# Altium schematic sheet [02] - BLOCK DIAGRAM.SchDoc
size A3; DocumentNumber: 2; SheetNumber: 2; SheetTotal: 4
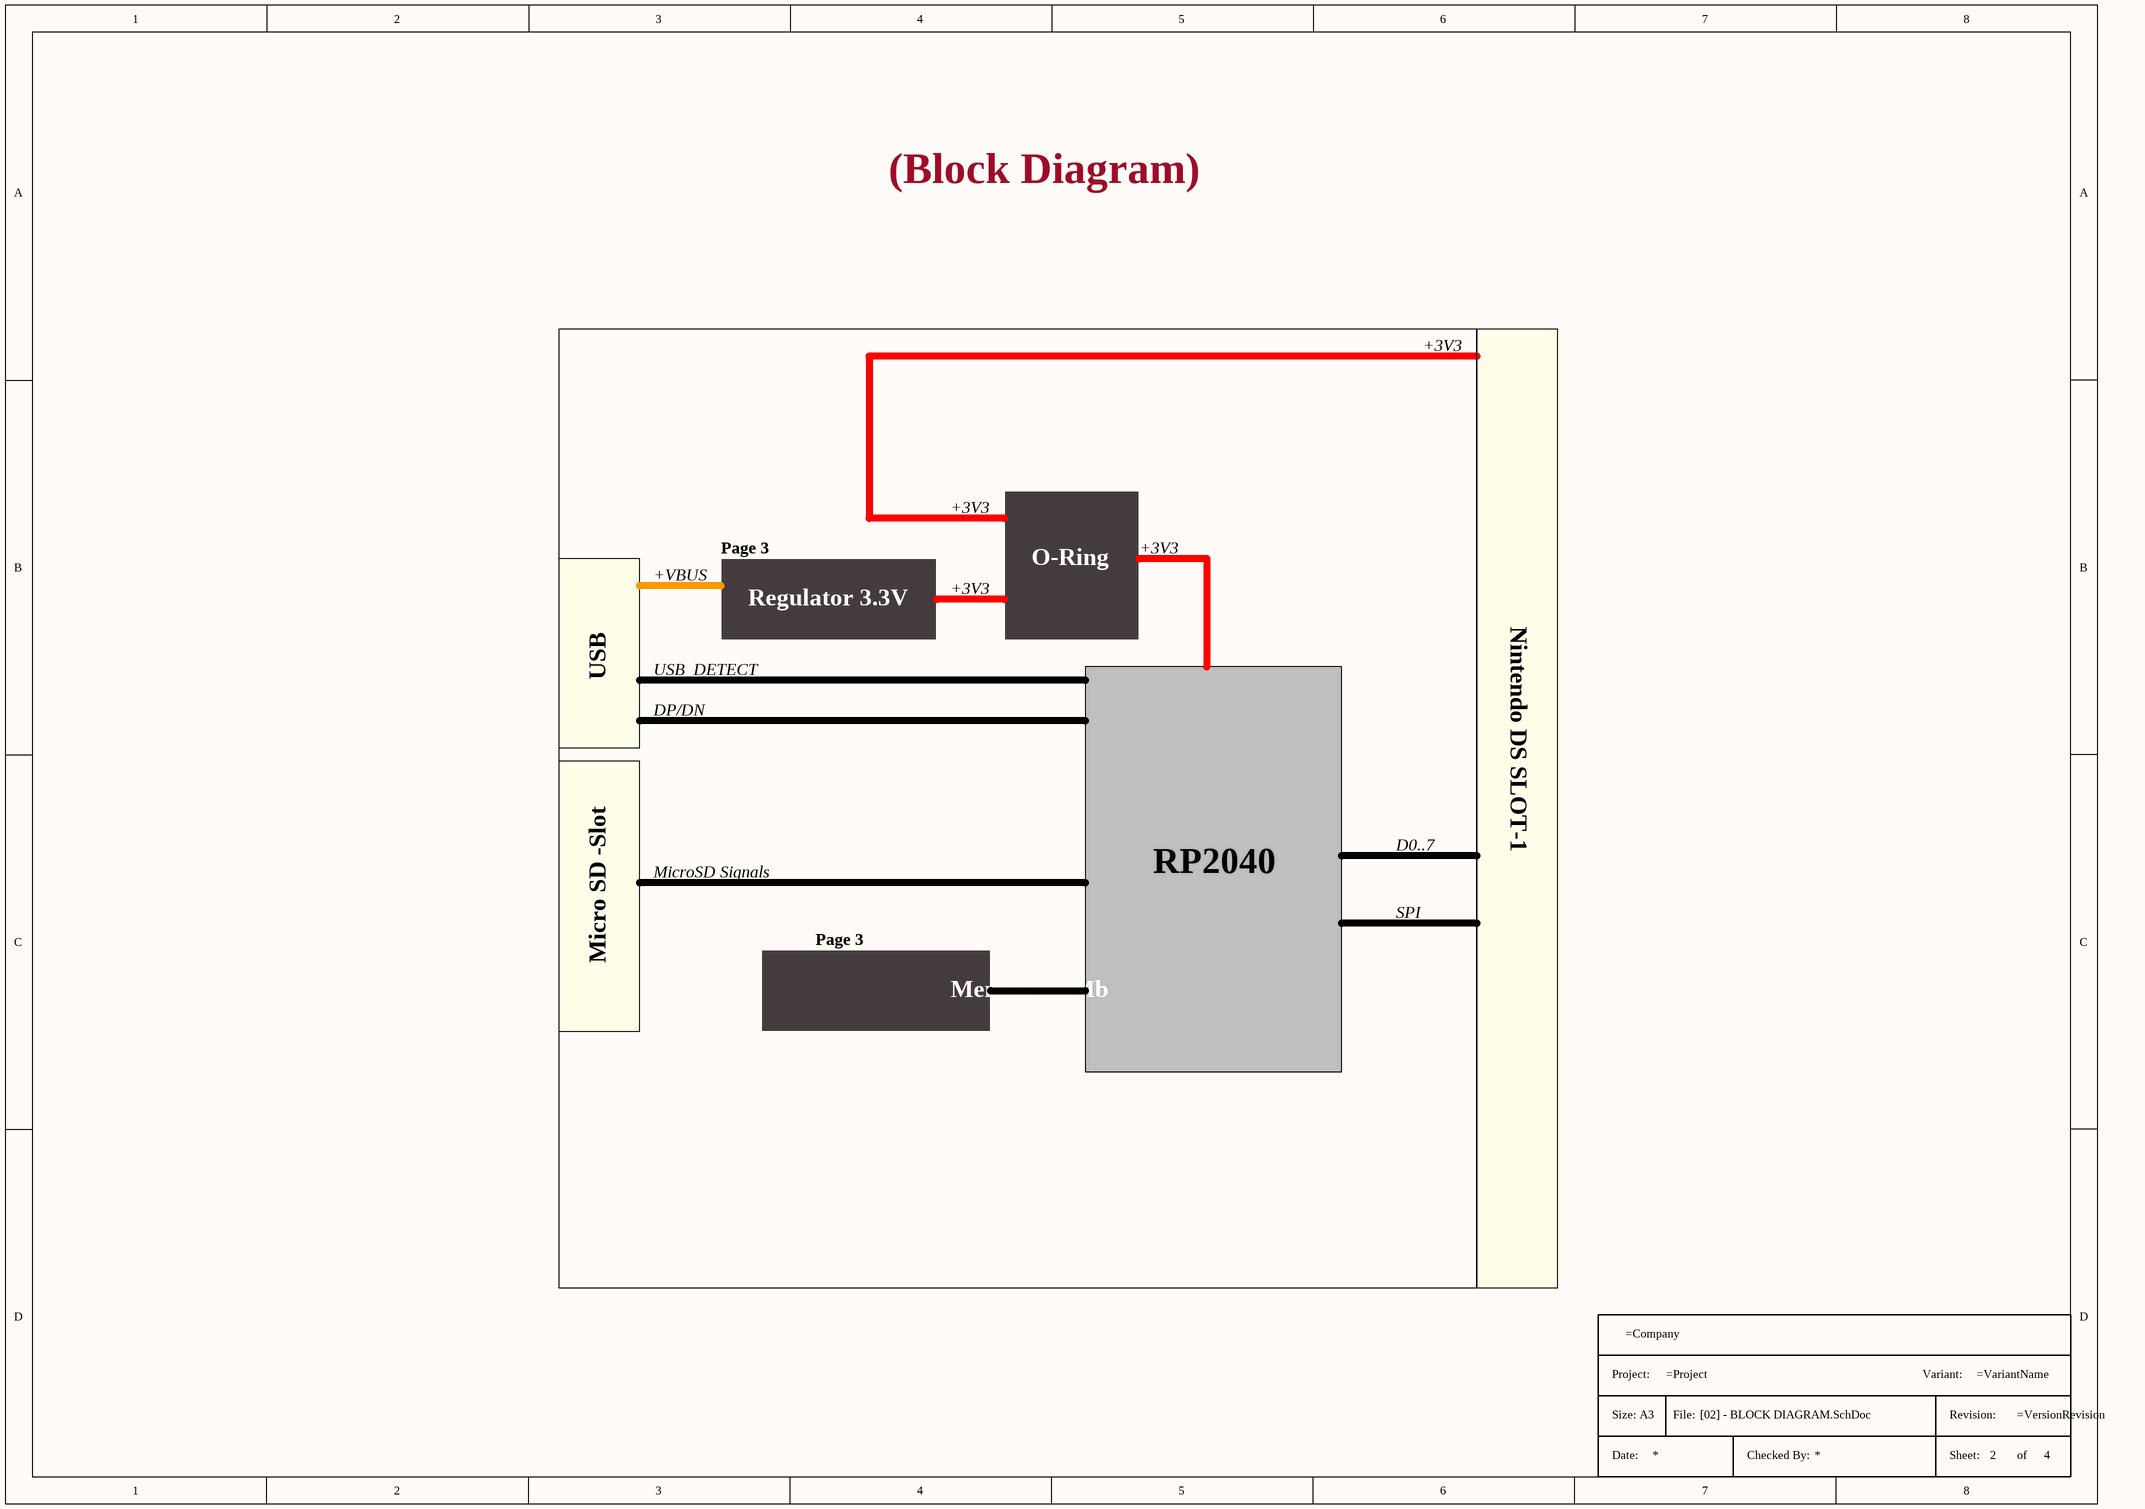
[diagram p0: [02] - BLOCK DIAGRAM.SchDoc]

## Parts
*  Title Block A3  (value not drawn)  (graphical)

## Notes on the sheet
- (Block Diagram)
- +3V3
- +VBUS
- Page 3
- O-Ring
- Regulator 3.3V
- Nintendo DS SLOT-1
- USB
- DP/DN
- USB_DETECT
- D0..7
- MicroSD Signals
- RP2040
- SPI
- Micro SD -Slot
- Memory 16Mb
